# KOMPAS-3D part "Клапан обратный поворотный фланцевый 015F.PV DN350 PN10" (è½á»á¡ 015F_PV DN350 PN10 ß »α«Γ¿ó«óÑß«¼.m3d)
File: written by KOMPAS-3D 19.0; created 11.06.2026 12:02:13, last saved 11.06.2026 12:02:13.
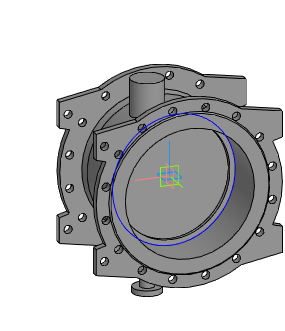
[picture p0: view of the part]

Document properties: Автор: Энергия; Полное имя файла: Z:\3.Личные\kachalov\001_3d для проектировщиков\5.5 Тип 015F.PV Клапан обратный поворотный с двумя эксцентриками\_stp_Клапан 015F.PV DN300-DN1200 с противовесом\Клапан 015F_PV DN350 PN10 с противовесом.m3d

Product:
- Part/product: Клапан обратный поворотный фланцевый 015F.PV DN350 PN10

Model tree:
1. Операция без истории:1
2. Сплайн:1
     Координата Y = 30; Координата Z = 175; Вес = 1; Координата X = 350; Координата Y = 76.0784; Координата Z = 175; Вес = 0.333333; Координата X = 350; Координата Y = 76.0784; Координата Z = -175; Вес = 0.333333; Координата Y = 30; Координата Z = -175; Вес = 1; Координата X = -350; Координата Y = -16.0784; Координата Z = -175; Вес = 0.333333; Координата X = -350; Координата Y = -16.0784; Координата Z = 175; Вес = 0.333333; Порядок = 4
